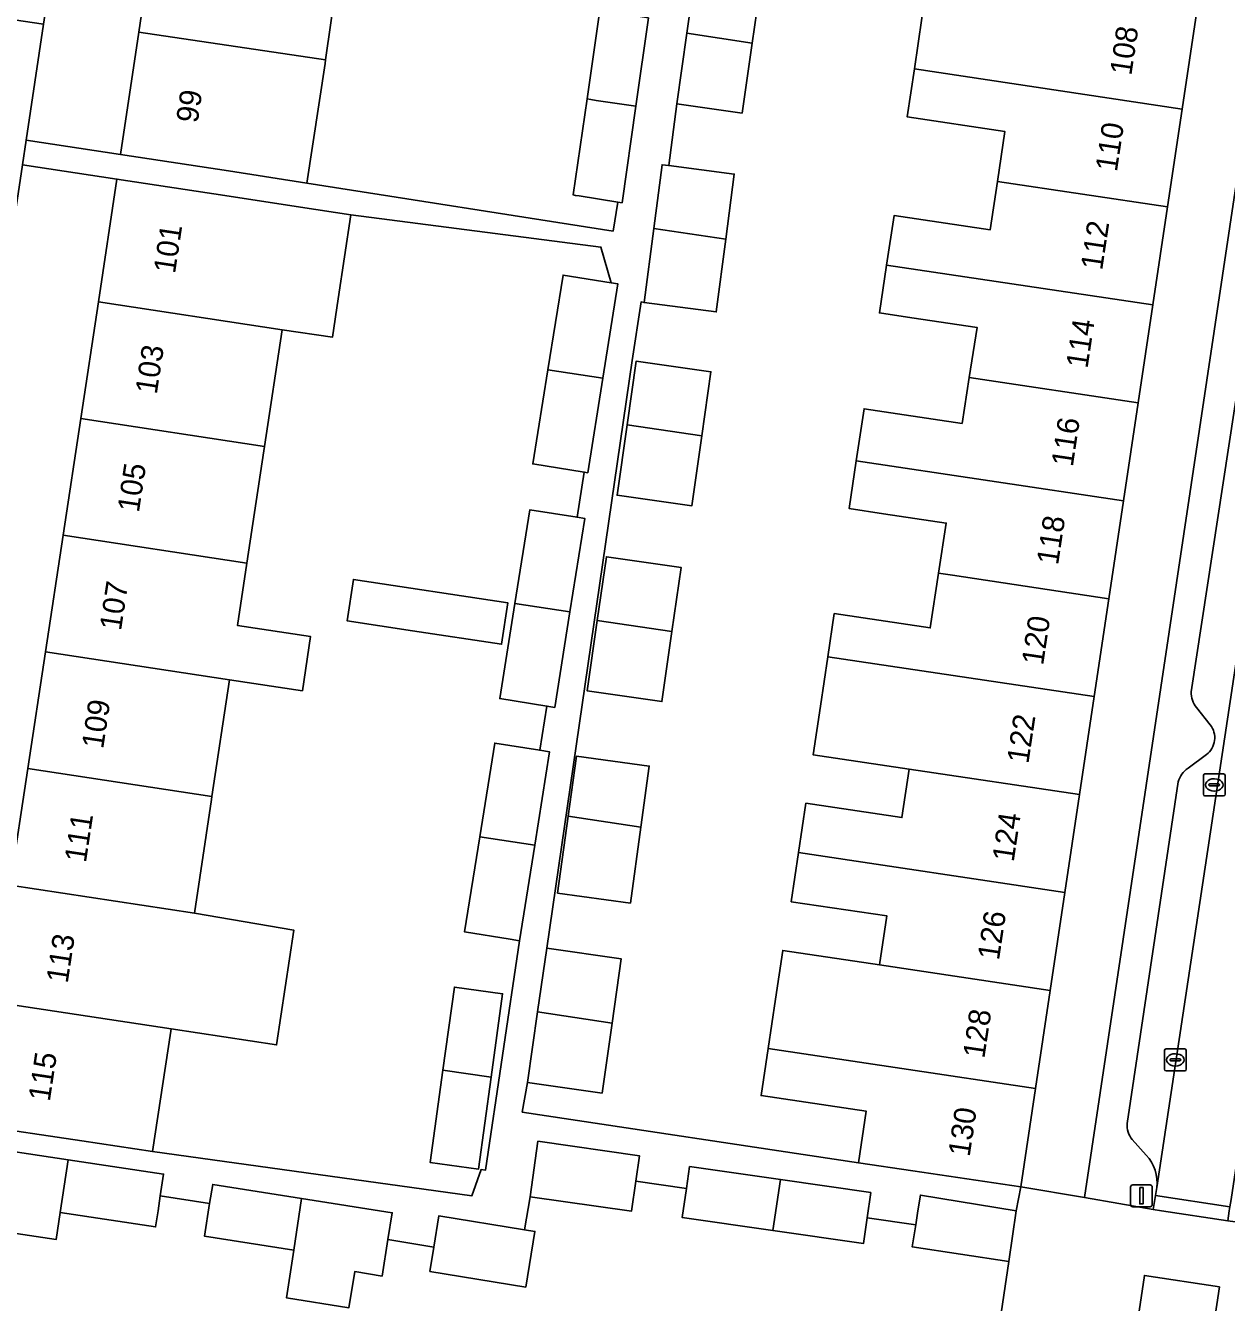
# Model space of a CAD drawing. Extents: x 163008 to 163854, y 382777 to 383982.
# Drawn here: x 163559.8 to 163614.8, y 383245.8 to 383304.2 of the extents above; entities that cross this region are included whole.
import ezdxf

# ---------------------------------------------------------------- set-up
doc = ezdxf.new("R2010")
doc.units = 0
for name, color, linetype in [('IMGEO_Erf', 7, 'Continuous'), ('IMGEO_Kolk', 7, 'Continuous'), ('IMGEO_Lichtmast', 7, 'Continuous'), ('IMGEO_Muur', 7, 'Continuous'), ('IMGEO_Pand', 7, 'Continuous'), ('IMGEO_Pand_nummerreeks', 7, 'Continuous'), ('IMGEO_Parkeervlak_open', 7, 'Continuous'), ('IMGEO_Rijbaan_lokaal_open', 7, 'Continuous'), ('IMGEO_Voetpad_open', 7, 'Continuous')]:
    doc.layers.add(name, color=color, linetype=linetype)

msp = doc.modelspace()

# ---------------------------------------------------------------- linework, layer by layer
at = {"layer": 'IMGEO_Erf'}
for points in [[(163567.416, 383319.964), (163568.214, 383325.305), (163569.013, 383330.646), (163569.798, 383335.9), (163565.502, 383336.544), (163560.664, 383304.297), (163559.867, 383298.985), (163564.184, 383298.337), (163565.022, 383303.942), (163565.82, 383309.283), (163566.618, 383314.624)], [(163617.064, 383309.129), (163614.133, 383309.568), (163613.435, 383304.901), (163612.765, 383300.418), (163612.095, 383295.936), (163611.424, 383291.454), (163610.754, 383286.972), (163610.084, 383282.49), (163609.414, 383278.008), (163608.744, 383273.526), (163608.073, 383269.044), (163607.403, 383264.561), (163606.733, 383260.079), (163606.062, 383255.594), (163605.388, 383251.086), (163608.303, 383250.604)], [(163561.554, 383280.911), (163562.362, 383286.25), (163563.169, 383291.59), (163564.019, 383297.21), (163559.698, 383297.858), (163553.2, 383254.546), (163556.521, 383254.072), (163556.582, 383254.063), (163557.474, 383253.935), (163558.324, 383259.553), (163559.131, 383264.893), (163559.94, 383270.232), (163560.746, 383275.572)], [(163581.309, 383271.398), (163583.373, 383271.069), (163583.696, 383273.092), (163581.543, 383273.436), (163582.237, 383277.783), (163582.923, 383282.077), (163585.075, 383281.733), (163585.405, 383283.799), (163583.053, 383284.175), (163583.741, 383288.481), (163584.434, 383292.816), (163586.632, 383292.464), (163586.169, 383294.1), (163574.725, 383295.571), (163574.146, 383291.736), (163573.88, 383289.972), (163571.586, 383290.318), (163570.768, 383284.979), (163570.736, 383284.768), (163569.966, 383279.639), (163569.537, 383276.784), (163572.878, 383276.281), (163572.505, 383273.794), (163569.17, 383274.298), (163568.368, 383268.957), (163568.348, 383268.825), (163567.566, 383263.618), (163572.112, 383262.839), (163571.323, 383257.588), (163566.494, 383258.318), (163566.479, 383258.216), (163565.651, 383252.707), (163580.263, 383250.683), (163580.685, 383251.88), (163580.886, 383251.852), (163582.44, 383262.356), (163582.009, 383262.425), (163579.929, 383262.757), (163580.623, 383267.104)], [(163590.325, 383282.253), (163586.91, 383282.741), (163587.372, 383285.97), (163587.788, 383288.883), (163591.202, 383288.395), (163590.783, 383285.459)], [(163588.958, 383273.296), (163585.543, 383273.784), (163586.005, 383277.013), (163586.421, 383279.926), (163589.835, 383279.438), (163589.416, 383276.502)], [(163574.557, 383276.991), (163574.844, 383278.889), (163581.906, 383277.821), (163581.62, 383275.924), (163577.548, 383276.539)], [(163588.381, 383270.349), (163587.996, 383267.552), (163587.516, 383264.075), (163584.188, 383264.534), (163584.672, 383268.05), (163585.053, 383270.808)], [(163578.941, 383256.436), (163579.463, 383260.233), (163581.666, 383259.93), (163581.14, 383256.104), (163580.562, 383251.897), (163578.358, 383252.2)]]:
    msp.add_lwpolyline(points, close=True, dxfattribs=at)
for points in [[(163574.317, 383307.87), (163573.568, 383302.665), (163573.543, 383302.501), (163572.716, 383297.027), (163586.723, 383294.829), (163586.936, 383296.159), (163585.172, 383296.441), (163585.011, 383296.467), (163584.905, 383296.484), (163585.533, 383300.878), (163586.115, 383304.943)], [(163593.512, 383306.37), (163593.092, 383303.437), (163592.633, 383300.229), (163589.642, 383300.656), (163589.274, 383297.831), (163592.269, 383297.44), (163591.88, 383294.456), (163591.447, 383291.132), (163588.147, 383291.563), (163588.004, 383291.588), (163587.603, 383288.909), (163583.688, 383262.011), (163587.102, 383261.523), (163586.683, 383258.587), (163586.225, 383255.381), (163582.81, 383255.869), (163582.568, 383254.515), (163597.963, 383252.196), (163598.315, 383254.55), (163593.497, 383255.271), (163593.819, 383257.426), (163594.156, 383259.68), (163594.489, 383261.912), (163598.92, 383261.249), (163599.255, 383263.488), (163594.881, 383264.142), (163595.216, 383266.385), (163595.554, 383268.646), (163599.944, 383267.989), (163600.276, 383270.21), (163595.881, 383270.867), (163596.213, 383273.085), (163596.552, 383275.35), (163596.848, 383277.33), (163601.242, 383276.673), (163601.616, 383279.174), (163601.977, 383281.466), (163599.103, 383281.896), (163597.531, 383282.131), (163597.858, 383284.319), (163598.215, 383286.704), (163599.745, 383286.475), (163602.696, 383286.033), (163603.026, 383288.129), (163603.387, 383290.419), (163600.402, 383290.866), (163598.918, 383291.088), (163599.245, 383293.277), (163599.584, 383295.543), (163603.982, 383294.886), (163604.313, 383297.101), (163604.655, 383299.386), (163600.187, 383300.054), (163600.516, 383302.251), (163600.863, 383304.571)], [(163603.164, 383236.369), (163604.845, 383247.675), (163600.42, 383248.34), (163600.58, 383249.36), (163598.355, 383249.679), (163598.186, 383248.497), (163594.041, 383249.091), (163589.889, 383249.686), (163590.08, 383251.015), (163587.766, 383251.347), (163587.572, 383249.98), (163582.924, 383250.64), (163582.677, 383249.13), (163583.146, 383249.053), (163582.73, 383246.507), (163578.34, 383247.224), (163578.522, 383248.335), (163576.422, 383248.678), (163576.158, 383247.011), (163574.9, 383247.21), (163574.638, 383245.557), (163571.781, 383246.009), (163572.11, 383248.193), (163568.027, 383248.84), (163568.262, 383250.323), (163566.003, 383250.681), (163565.901, 383250), (163565.79, 383249.255), (163561.426, 383249.91), (163561.241, 383248.683), (163555.832, 383249.496)]]:
    msp.add_lwpolyline(points, dxfattribs=at)
at = {"layer": 'IMGEO_Kolk'}
for p, q in [((163613.739, 383269.06), (163613.739, 383269.912)), ((163613.814, 383269.986), (163614.666, 383269.986)), ((163614.74, 383269.912), (163614.74, 383269.06)), ((163613.998, 383269.48), (163613.998, 383269.492)), ((163614.436, 383269.443), (163614.038, 383269.443)), ((163614.041, 383269.529), (163614.439, 383269.529)), ((163614.227, 383269.766), (163614.252, 383269.766)), ((163614.482, 383269.492), (163614.482, 383269.48)), ((163614.666, 383268.986), (163613.814, 383268.986)), ((163614.25, 383269.206), (163614.225, 383269.206)), ((163611.959, 383256.475), (163611.959, 383257.327)), ((163612.034, 383257.401), (163612.886, 383257.401)), ((163612.447, 383257.181), (163612.472, 383257.181)), ((163612.96, 383257.327), (163612.96, 383256.475)), ((163612.218, 383256.895), (163612.218, 383256.907)), ((163612.656, 383256.858), (163612.258, 383256.858)), ((163612.261, 383256.944), (163612.659, 383256.944)), ((163612.47, 383256.621), (163612.445, 383256.621)), ((163612.702, 383256.907), (163612.702, 383256.895)), ((163612.886, 383256.401), (163612.034, 383256.401))]:
    msp.add_line(p, q, dxfattribs=at)
for points in [[(163613.739, 383269.06), (163613.739, 383269.912)], [(163613.814, 383269.986), (163614.666, 383269.986)], [(163614.74, 383269.912), (163614.74, 383269.06)], [(163614.666, 383268.986), (163613.814, 383268.986)], [(163611.959, 383256.475), (163611.959, 383257.327)], [(163612.034, 383257.401), (163612.886, 383257.401)], [(163612.96, 383257.327), (163612.96, 383256.475)], [(163612.886, 383256.401), (163612.034, 383256.401)]]:
    msp.add_lwpolyline(points, dxfattribs=at)
for centre, radius, start, end in [((163613.816, 383269.91), 0.0765, 91.55205, 178.44795), ((163613.816, 383269.91), 0.0765, 91.55205, 178.44795), ((163614.664, 383269.91), 0.0765, 1.55205, 88.44795), ((163614.664, 383269.91), 0.0765, 1.55205, 88.44795), ((163614.038, 383269.489), 0.0403, 85.87752, 175.75265), ((163614.035, 383269.479), 0.0366, 178.93798, 274.71019), ((163614.439, 383269.486), 0.043, 264.86636, 352.45326), ((163614.443, 383269.491), 0.0386, 1.73085, 96.63898), ((163613.816, 383269.062), 0.0765, 181.55205, 268.44795), ((163613.816, 383269.062), 0.0765, 181.55205, 268.44795), ((163614.664, 383269.062), 0.0765, 271.55205, 358.44795), ((163614.664, 383269.062), 0.0765, 271.55205, 358.44795), ((163612.036, 383257.325), 0.0765, 91.55205, 178.44795), ((163612.036, 383257.325), 0.0765, 91.55205, 178.44795), ((163612.884, 383257.325), 0.0765, 1.55205, 88.44795), ((163612.884, 383257.325), 0.0765, 1.55205, 88.44795), ((163612.036, 383256.477), 0.0765, 181.55205, 268.44795), ((163612.036, 383256.477), 0.0765, 181.55205, 268.44795), ((163612.258, 383256.904), 0.0403, 85.87752, 175.75265), ((163612.255, 383256.894), 0.0366, 178.93798, 274.71019), ((163612.659, 383256.901), 0.043, 264.86636, 352.45326), ((163612.663, 383256.906), 0.0386, 1.73085, 96.63898), ((163612.884, 383256.477), 0.0765, 271.55205, 358.44795), ((163612.884, 383256.477), 0.0765, 271.55205, 358.44795)]:
    msp.add_arc(centre, radius, start, end, dxfattribs=at)
for centre, major_axis, ratio, start_param, end_param in [((163614.226, 383269.486), (-0.387, 0.002), 0.722429, 4.712389, 7.853982), ((163614.251, 383269.486), (-0.39, 0.002), 0.717154, 1.570796, 4.712389), ((163612.446, 383256.901), (-0.387, 0.002), 0.722429, 4.712389, 7.853982), ((163612.471, 383256.901), (-0.39, 0.002), 0.717154, 1.570796, 4.712389)]:
    msp.add_ellipse(centre, major_axis=major_axis, ratio=ratio, start_param=start_param, end_param=end_param, dxfattribs=at)
at = {"layer": 'IMGEO_Lichtmast'}
for p, q in [((163610.41, 383250.283), (163610.41, 383251.083)), ((163610.41, 383251.083), (163610.41, 383250.283)), ((163610.51, 383251.183), (163611.3, 383251.183)), ((163611.3, 383251.183), (163610.51, 383251.183)), ((163611.4, 383251.083), (163611.4, 383250.283)), ((163611.4, 383250.283), (163611.4, 383251.083)), ((163611.3, 383250.183), (163610.51, 383250.183)), ((163610.51, 383250.183), (163611.3, 383250.183))]:
    msp.add_line(p, q, dxfattribs=at)
msp.add_lwpolyline([(163610.83, 383251.058), (163610.98, 383251.058), (163610.98, 383250.308), (163610.83, 383250.308), (163610.83, 383251.058)], dxfattribs=at)
for centre, start, end in [((163610.51, 383251.083), 90, 180), ((163610.51, 383251.083), 90, 180), ((163611.3, 383251.083), 0, 90), ((163611.3, 383251.083), 360, 90), ((163610.51, 383250.283), 180, 270), ((163610.51, 383250.283), 180, 270), ((163611.3, 383250.283), 270, 0), ((163611.3, 383250.283), 270, 0)]:
    msp.add_arc(centre, 0.1, start, end, dxfattribs=at)
at = {"layer": 'IMGEO_Muur'}
msp.add_lwpolyline([(163603.164, 383236.369), (163604.845, 383247.675)], dxfattribs=at)
at = {"layer": 'IMGEO_Pand'}
for points in [[(163574.317, 383307.87), (163574.338, 383308.01), (163565.82, 383309.283), (163565.022, 383303.942), (163573.568, 383302.665)], [(163593.512, 383306.37), (163590.774, 383306.762), (163590.52, 383306.798), (163590.104, 383303.885), (163593.092, 383303.437)], [(163613.435, 383304.901), (163605.638, 383306.068), (163601.187, 383306.734), (163600.863, 383304.571), (163600.516, 383302.251), (163612.765, 383300.418)], [(163588.35, 383304.587), (163586.359, 383304.905), (163586.115, 383304.943), (163585.533, 383300.878), (163585.711, 383300.851), (163585.959, 383300.814), (163587.771, 383300.543)], [(163573.543, 383302.501), (163573.568, 383302.665), (163565.022, 383303.942), (163564.184, 383298.337), (163569.129, 383297.594), (163572.716, 383297.027)], [(163593.092, 383303.437), (163590.104, 383303.885), (163589.642, 383300.656), (163592.633, 383300.229)], [(163612.095, 383295.936), (163612.765, 383300.418), (163600.516, 383302.251), (163600.187, 383300.054), (163604.655, 383299.386), (163604.313, 383297.101)], [(163587.771, 383300.543), (163585.959, 383300.814), (163585.711, 383300.851), (163585.533, 383300.878), (163584.905, 383296.484), (163585.011, 383296.467), (163585.172, 383296.441), (163586.936, 383296.159), (163587.139, 383296.127)], [(163589.274, 383297.831), (163588.97, 383297.871), (163588.589, 383294.949), (163591.88, 383294.456), (163592.269, 383297.44)], [(163574.725, 383295.571), (163572.423, 383295.919), (163568.964, 383296.467), (163564.019, 383297.21), (163563.169, 383291.59), (163571.586, 383290.318), (163573.88, 383289.972), (163574.146, 383291.736)], [(163599.245, 383293.277), (163611.424, 383291.454), (163612.095, 383295.936), (163604.313, 383297.101), (163603.982, 383294.886), (163599.584, 383295.543)], [(163588.589, 383294.949), (163588.147, 383291.563), (163591.447, 383291.132), (163591.88, 383294.456)], [(163586.945, 383292.414), (163586.632, 383292.464), (163584.434, 383292.816), (163583.741, 383288.481), (163586.256, 383288.101)], [(163611.424, 383291.454), (163599.245, 383293.277), (163598.918, 383291.088), (163600.402, 383290.866), (163603.387, 383290.419), (163603.026, 383288.129), (163610.754, 383286.972)], [(163571.586, 383290.318), (163563.169, 383291.59), (163562.362, 383286.25), (163570.768, 383284.979)], [(163590.783, 383285.459), (163591.202, 383288.395), (163587.788, 383288.883), (163587.372, 383285.97)], [(163586.256, 383288.101), (163583.741, 383288.481), (163583.053, 383284.175), (163585.405, 383283.799), (163585.564, 383283.774)], [(163610.754, 383286.972), (163603.026, 383288.129), (163602.696, 383286.033), (163599.745, 383286.475), (163598.215, 383286.704), (163597.858, 383284.319), (163610.084, 383282.49)], [(163570.736, 383284.768), (163570.768, 383284.979), (163562.362, 383286.25), (163561.554, 383280.911), (163569.966, 383279.639)], [(163590.783, 383285.459), (163587.372, 383285.97), (163586.91, 383282.741), (163590.325, 383282.253)], [(163610.084, 383282.49), (163597.858, 383284.319), (163597.531, 383282.131), (163599.103, 383281.896), (163601.977, 383281.466), (163601.616, 383279.174), (163602.255, 383279.078), (163609.414, 383278.008)], [(163585.435, 383281.676), (163585.075, 383281.733), (163582.923, 383282.077), (163582.237, 383277.783), (163584.752, 383277.403)], [(163569.966, 383279.639), (163561.554, 383280.911), (163560.746, 383275.572), (163569.17, 383274.298), (163572.505, 383273.794), (163572.878, 383276.281), (163569.537, 383276.784)], [(163589.416, 383276.502), (163589.835, 383279.438), (163586.421, 383279.926), (163586.005, 383277.013)], [(163574.844, 383278.889), (163574.557, 383276.991), (163577.548, 383276.539), (163581.62, 383275.924), (163581.906, 383277.821)], [(163609.414, 383278.008), (163602.255, 383279.078), (163601.616, 383279.174), (163601.242, 383276.673), (163596.848, 383277.33), (163596.552, 383275.35), (163608.744, 383273.526)], [(163584.752, 383277.403), (163582.237, 383277.783), (163581.543, 383273.436), (163583.696, 383273.092), (163584.054, 383273.035)], [(163589.416, 383276.502), (163586.005, 383277.013), (163585.543, 383273.784), (163588.958, 383273.296)], [(163569.17, 383274.298), (163560.746, 383275.572), (163559.94, 383270.232), (163568.368, 383268.957)], [(163596.552, 383275.35), (163596.213, 383273.085), (163595.881, 383270.867), (163600.276, 383270.21), (163608.073, 383269.044), (163608.744, 383273.526)], [(163583.821, 383270.997), (163583.373, 383271.069), (163581.309, 383271.398), (163580.623, 383267.104), (163583.138, 383266.724)], [(163587.996, 383267.552), (163588.381, 383270.349), (163585.053, 383270.808), (163584.672, 383268.05)], [(163568.348, 383268.825), (163568.368, 383268.957), (163559.94, 383270.232), (163559.131, 383264.893), (163567.566, 383263.618)], [(163600.276, 383270.21), (163599.944, 383267.989), (163595.554, 383268.646), (163595.216, 383266.385), (163607.403, 383264.561), (163608.073, 383269.044)], [(163587.996, 383267.552), (163584.672, 383268.05), (163584.188, 383264.534), (163587.516, 383264.075)], [(163583.138, 383266.724), (163580.623, 383267.104), (163579.929, 383262.757), (163582.009, 383262.425), (163582.44, 383262.356)], [(163598.92, 383261.249), (163606.733, 383260.079), (163607.403, 383264.561), (163595.216, 383266.385), (163594.881, 383264.142), (163599.255, 383263.488)], [(163572.112, 383262.839), (163567.566, 383263.618), (163559.131, 383264.893), (163558.324, 383259.553), (163566.494, 383258.318), (163571.323, 383257.588)], [(163583.272, 383259.098), (163586.683, 383258.587), (163587.102, 383261.523), (163583.688, 383262.011)], [(163606.733, 383260.079), (163598.92, 383261.249), (163594.489, 383261.912), (163594.156, 383259.68), (163593.819, 383257.426), (163606.062, 383255.594)], [(163578.941, 383256.436), (163581.14, 383256.104), (163581.666, 383259.93), (163579.463, 383260.233)], [(163566.479, 383258.216), (163566.494, 383258.318), (163558.324, 383259.553), (163557.474, 383253.935), (163562.419, 383253.192), (163565.651, 383252.707)], [(163583.272, 383259.098), (163582.81, 383255.869), (163586.225, 383255.381), (163586.683, 383258.587)], [(163593.819, 383257.426), (163593.497, 383255.271), (163598.315, 383254.55), (163597.963, 383252.196), (163600.443, 383251.825), (163605.388, 383251.086), (163606.062, 383255.594)], [(163581.14, 383256.104), (163578.941, 383256.436), (163578.358, 383252.2), (163580.562, 383251.897)], [(163561.791, 383252.334), (163557.338, 383253.003), (163556.389, 383253.146), (163555.909, 383250), (163555.832, 383249.496), (163561.241, 383248.683), (163561.426, 383249.91)], [(163587.932, 383252.515), (163583.284, 383253.175), (163582.924, 383250.64), (163587.572, 383249.98), (163587.766, 383251.347)], [(163566.003, 383250.681), (163566.152, 383251.679), (163561.791, 383252.334), (163561.426, 383249.91), (163565.79, 383249.255), (163565.901, 383250)], [(163594.391, 383251.421), (163590.224, 383252.018), (163590.08, 383251.015), (163589.889, 383249.686), (163594.041, 383249.091)], [(163598.52, 383250.829), (163594.391, 383251.421), (163594.041, 383249.091), (163598.186, 383248.497), (163598.355, 383249.679)], [(163572.466, 383250.56), (163568.401, 383251.203), (163568.262, 383250.323), (163568.027, 383248.84), (163572.11, 383248.193)], [(163605.18, 383250), (163600.792, 383250.711), (163600.68, 383250), (163600.58, 383249.36), (163600.42, 383248.34), (163604.845, 383247.675)], [(163576.422, 383248.678), (163576.616, 383249.902), (163572.466, 383250.56), (163572.11, 383248.193), (163571.781, 383246.009), (163574.638, 383245.557), (163574.9, 383247.21), (163576.158, 383247.011)], [(163583.146, 383249.053), (163582.677, 383249.13), (163578.756, 383249.77), (163578.522, 383248.335), (163578.34, 383247.224), (163582.73, 383246.507)]]:
    msp.add_lwpolyline(points, close=True, dxfattribs=at)
at = {"layer": 'IMGEO_Parkeervlak_open'}
for points in [[(163611.614, 383251.055), (163618.49, 383296.655)], [(163616.373, 383294.574), (163613.188, 383273.75)], [(163613.428, 383273.027), (163614.057, 383272.232)], [(163613.885, 383270.87), (163613.038, 383270.258)], [(163612.591, 383269.625), (163610.255, 383253.988)], [(163610.477, 383253.258), (163611.125, 383252.541)]]:
    msp.add_lwpolyline(points, dxfattribs=at)
for centre, radius, start, end in [((163614.193, 383273.682), 1.007, 176.14649, 220.58071), ((163613.293, 383271.637), 0.968, 307.66569, 37.93933), ((163613.676, 383269.333), 1.123, 124.59448, 164.94901), ((163611.243, 383253.89), 0.993, 174.31196, 219.51808), ((163609.731, 383251.259), 1.894, 353.82781, 42.60198)]:
    msp.add_arc(centre, radius, start, end, dxfattribs=at)
at = {"layer": 'IMGEO_Rijbaan_lokaal_open'}
for points in [[(163614.953, 383250.174), (163615.006, 383250.516), (163621.871, 383296.439), (163621.924, 383296.792), (163618.586, 383297.246), (163618.543, 383297.004), (163618.49, 383296.655), (163611.614, 383251.055), (163611.551, 383250.689)], [(163614.953, 383250.174), (163611.551, 383250.689), (163611.443, 383250.058), (163611.826, 383250), (163614.854, 383249.541), (163614.926, 383250)], [(163610.88, 383222.652), (163614.476, 383246.512), (163611.042, 383247.039), (163607.483, 383223.163)]]:
    msp.add_lwpolyline(points, close=True, dxfattribs=at)
at = {"layer": 'IMGEO_Voetpad_open'}
for points in [[(163629.103, 383367.415), (163629.166, 383367.856), (163629.256, 383368.49), (163626.017, 383368.942), (163617.252, 383310.387), (163617.064, 383309.129), (163608.303, 383250.604), (163611.443, 383250.058), (163611.551, 383250.689), (163611.614, 383251.055)], [(163557.338, 383253.003), (163561.791, 383252.334), (163566.152, 383251.679), (163566.003, 383250.681), (163568.262, 383250.323), (163568.401, 383251.203), (163572.466, 383250.56), (163576.616, 383249.902), (163576.422, 383248.678), (163578.522, 383248.335), (163578.756, 383249.77), (163582.677, 383249.13), (163582.924, 383250.64), (163583.284, 383253.175), (163587.932, 383252.515), (163587.766, 383251.347), (163590.08, 383251.015), (163590.224, 383252.018), (163594.391, 383251.421), (163598.52, 383250.829), (163598.355, 383249.679), (163600.58, 383249.36), (163600.68, 383250), (163600.792, 383250.711), (163605.18, 383250), (163605.388, 383251.086), (163600.443, 383251.825), (163597.963, 383252.196), (163582.568, 383254.515), (163582.81, 383255.869), (163583.272, 383259.098), (163583.688, 383262.011), (163587.603, 383288.909), (163588.004, 383291.588), (163588.147, 383291.563), (163588.589, 383294.949), (163588.97, 383297.871), (163589.274, 383297.831), (163589.642, 383300.656), (163590.104, 383303.885), (163590.52, 383306.798)], [(163588.35, 383304.587), (163587.771, 383300.543), (163587.139, 383296.127), (163586.936, 383296.159), (163586.723, 383294.829), (163572.716, 383297.027), (163569.129, 383297.594), (163564.184, 383298.337), (163559.867, 383298.985), (163559.698, 383297.858), (163564.019, 383297.21), (163568.964, 383296.467), (163572.423, 383295.919), (163574.725, 383295.571), (163586.169, 383294.1), (163586.632, 383292.464), (163586.945, 383292.414), (163586.256, 383288.101), (163585.564, 383283.774), (163585.405, 383283.799), (163585.075, 383281.733), (163585.435, 383281.676), (163584.752, 383277.403), (163584.054, 383273.035), (163583.696, 383273.092), (163583.373, 383271.069), (163583.821, 383270.997), (163583.138, 383266.724), (163582.44, 383262.356), (163580.886, 383251.852), (163580.685, 383251.88), (163580.263, 383250.683), (163565.651, 383252.707), (163562.419, 383253.192), (163557.474, 383253.935)], [(163559.698, 383297.858), (163559.867, 383298.985), (163560.664, 383304.297), (163558.474, 383304.626), (163557.63, 383304.071)], [(163613.188, 383273.75), (163616.373, 383294.574)], [(163614.057, 383272.232), (163613.428, 383273.027)], [(163613.038, 383270.258), (163613.885, 383270.87)], [(163610.255, 383253.988), (163612.591, 383269.625)], [(163611.125, 383252.541), (163610.477, 383253.258)]]:
    msp.add_lwpolyline(points, dxfattribs=at)
msp.add_lwpolyline([(163618.941, 383233.649), (163620.614, 383244.998), (163620.668, 383245.357), (163620.284, 383245.414), (163620.803, 383248.742), (163618.346, 383249.06), (163614.854, 383249.541), (163611.826, 383250), (163611.443, 383250.058), (163608.303, 383250.604), (163605.388, 383251.086), (163605.18, 383250), (163604.845, 383247.675), (163603.164, 383236.369), (163601.906, 383228.141), (163601.286, 383224.16), (163607.483, 383223.163), (163611.042, 383247.039), (163614.476, 383246.512), (163610.88, 383222.652), (163617.111, 383221.572), (163617.75, 383225.735)], close=True, dxfattribs=at)
for centre, radius, start, end in [((163614.193, 383273.682), 1.007, 176.14649, 220.58071), ((163613.293, 383271.637), 0.968, 307.66569, 37.93933), ((163613.676, 383269.333), 1.123, 124.59448, 164.94901), ((163611.243, 383253.89), 0.993, 174.31196, 219.51808), ((163609.731, 383251.259), 1.894, 353.82781, 42.60198)]:
    msp.add_arc(centre, radius, start, end, dxfattribs=at)

# ---------------------------------------------------------------- texts
at = {"layer": 'IMGEO_Pand_nummerreeks'}
for s, rotation, p in [('108', 81.49752, (163610.442, 383301.923)), ('99', 81.49752, (163567.711, 383299.744)), ('110', 81.49539, (163609.782, 383297.514)), ('112', 81.49539, (163609.108, 383293.01)), ('101', 81.40011, (163566.677, 383292.855)), ('114', 81.49752, (163608.437, 383288.514)), ('103', 81.40011, (163565.842, 383287.332)), ('116', 81.49752, (163607.764, 383284.015)), ('105', 81.40011, (163565.024, 383281.923)), ('118', 81.49752, (163607.091, 383279.519)), ('107', 81.40011, (163564.206, 383276.514)), ('120', 81.49752, (163606.406, 383274.931)), ('109', 81.40011, (163563.388, 383271.104)), ('122', 81.49539, (163605.732, 383270.428)), ('111', 81.40011, (163562.6, 383265.898)), ('124', 81.49539, (163605.059, 383265.931)), ('126', 81.49539, (163604.387, 383261.432)), ('113', 81.40011, (163561.765, 383260.376)), ('128', 81.49752, (163603.715, 383256.937)), ('115', 81.40011, (163560.946, 383254.967)), ('130', 81.49539, (163603.042, 383252.439))]:
    msp.add_text(s, height=1, rotation=rotation, dxfattribs=at).set_placement(p)

doc.saveas('drawing.dxf')
